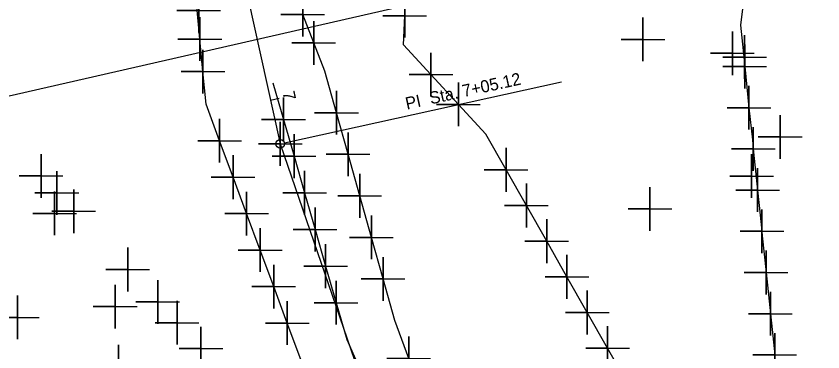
# Model space of a CAD drawing. Extents: x 2260968 to 2264340, y 653057 to 655850.
# Drawn here: x 2261657.4 to 2261749.7, y 655055 to 655093.4 of the extents above; entities that cross this region are included whole.
import ezdxf

# ---------------------------------------------------------------- set-up
doc = ezdxf.new("R2010")
doc.units = 0
for name, color, linetype in [('CL_X_Construction', 7, 'Continuous'), ('Default', 7, 'Continuous'), ('GE_X_CL_10', 7, 'Continuous'), ('GK_Patterns2', 7, 'Continuous')]:
    doc.layers.add(name, color=color, linetype=linetype)

msp = doc.modelspace()

# ---------------------------------------------------------------- linework, layer by layer
at = {"layer": 'CL_X_Construction'}
for p, q in [((2261663.661, 655187.525), (2261687.579, 655078.757)), ((2261663.661, 655187.525), (2261687.579, 655078.757)), ((2261687.579, 655078.757), (2261714.109, 655001.598)), ((2261687.579, 655078.757), (2261714.109, 655001.598))]:
    msp.add_line(p, q, dxfattribs=at)
at = {"layer": 'Default'}
for points in [[(2261678.254, 655093.992), (2261678.254, 655096.492), (2261678.254, 655093.992), (2261675.754, 655093.992), (2261678.254, 655093.992), (2261678.254, 655091.492), (2261678.254, 655093.992), (2261680.754, 655093.992)], [(2261690.155, 655093.53), (2261690.155, 655096.03), (2261690.155, 655093.53), (2261687.655, 655093.53), (2261690.155, 655093.53), (2261690.155, 655091.03), (2261690.155, 655093.53), (2261692.655, 655093.53)], [(2261701.833, 655093.401), (2261701.833, 655095.901), (2261701.833, 655093.401), (2261699.333, 655093.401), (2261701.833, 655093.401), (2261701.833, 655090.901), (2261701.833, 655093.401), (2261704.333, 655093.401)], [(2261740.728, 655096.117), (2261740.257, 655092.312), (2261740.748, 655087.601), (2261741.24, 655082.889), (2261741.625, 655079.201), (2261741.732, 655078.178), (2261741.923, 655076.347), (2261742.223, 655073.466), (2261742.405, 655071.722), (2261742.715, 655068.754), (2261742.769, 655068.23), (2261743.206, 655064.043), (2261743.698, 655059.331), (2261743.887, 655057.515), (2261744.189, 655054.62)], [(2261689.938, 655054.1), (2261688.389, 655058.269), (2261686.839, 655062.438), (2261685.289, 655066.607), (2261683.74, 655070.776), (2261682.19, 655074.945), (2261680.641, 655079.114), (2261679.091, 655083.283), (2261678.737, 655087.012), (2261678.382, 655090.741), (2261678.027, 655094.471)], [(2261678.382, 655090.741), (2261678.382, 655093.241), (2261678.382, 655090.741), (2261675.882, 655090.741), (2261678.382, 655090.741), (2261678.382, 655088.241), (2261678.382, 655090.741), (2261680.882, 655090.741)], [(2261720.425, 654990.805), (2261719.672, 654995.689), (2261718.919, 655000.572), (2261718.166, 655005.456), (2261717.413, 655010.339), (2261716.661, 655015.223), (2261715.064, 655019.556), (2261713.468, 655023.89), (2261711.871, 655028.223), (2261710.275, 655032.556), (2261708.678, 655036.889), (2261707.082, 655041.222), (2261705.485, 655045.556), (2261703.889, 655049.889), (2261702.292, 655054.222), (2261700.696, 655058.555), (2261699.362, 655063.307), (2261698.028, 655068.058), (2261696.694, 655072.81), (2261695.36, 655077.561), (2261694.026, 655082.313), (2261692.692, 655087.064), (2261691.423, 655090.297), (2261690.155, 655093.53)], [(2261727.371, 655051.318), (2261725.05, 655055.396), (2261722.729, 655059.473), (2261720.407, 655063.55), (2261718.086, 655067.627), (2261715.765, 655071.705), (2261713.444, 655075.782), (2261711.123, 655079.859), (2261707.975, 655083.264), (2261704.826, 655086.669), (2261701.677, 655090.074), (2261701.833, 655093.401)], [(2261729.105, 655090.698), (2261729.105, 655093.198), (2261729.105, 655090.698), (2261726.605, 655090.698), (2261729.105, 655090.698), (2261729.105, 655088.198), (2261729.105, 655090.698), (2261731.605, 655090.698)], [(2261691.423, 655090.297), (2261691.423, 655092.797), (2261691.423, 655090.297), (2261688.923, 655090.297), (2261691.423, 655090.297), (2261691.423, 655087.797), (2261691.423, 655090.297), (2261693.923, 655090.297)], [(2261739.351, 655089.119), (2261739.351, 655091.619), (2261739.351, 655089.119), (2261736.851, 655089.119), (2261739.351, 655089.119), (2261739.351, 655086.619), (2261739.351, 655089.119), (2261741.851, 655089.119)], [(2261740.746, 655088.678), (2261740.746, 655091.178), (2261740.746, 655088.678), (2261738.246, 655088.678), (2261740.746, 655088.678), (2261740.746, 655086.178), (2261740.746, 655088.678), (2261743.246, 655088.678)], [(2261678.737, 655087.012), (2261678.737, 655089.512), (2261678.737, 655087.012), (2261676.237, 655087.012), (2261678.737, 655087.012), (2261678.737, 655084.512), (2261678.737, 655087.012), (2261681.237, 655087.012)], [(2261740.748, 655087.601), (2261740.748, 655090.101), (2261740.748, 655087.601), (2261738.248, 655087.601), (2261740.748, 655087.601), (2261740.748, 655085.101), (2261740.748, 655087.601), (2261743.248, 655087.601)], [(2261704.826, 655086.669), (2261704.826, 655089.169), (2261704.826, 655086.669), (2261702.326, 655086.669), (2261704.826, 655086.669), (2261704.826, 655084.169), (2261704.826, 655086.669), (2261707.326, 655086.669)], [(2261686.753, 655085.733), (2261687.959, 655081.541), (2261689.164, 655077.349), (2261690.37, 655073.157), (2261691.575, 655068.965), (2261692.781, 655064.773), (2261693.986, 655060.581), (2261695.192, 655056.389), (2261697.028, 655052.215), (2261698.865, 655048.042), (2261700.701, 655043.868), (2261702.538, 655039.695), (2261704.375, 655035.521), (2261706.211, 655031.348), (2261708.048, 655027.174), (2261709.884, 655023.001), (2261711.721, 655018.827), (2261713.557, 655014.654), (2261714.248, 655009.793), (2261714.939, 655004.932), (2261715.63, 655000.071), (2261716.321, 654995.21), (2261717.012, 654990.35)], [(2261707.975, 655083.264), (2261707.975, 655085.764), (2261707.975, 655083.264), (2261705.475, 655083.264), (2261707.975, 655083.264), (2261707.975, 655080.764), (2261707.975, 655083.264), (2261710.475, 655083.264)], [(2261694.026, 655082.313), (2261694.026, 655084.813), (2261694.026, 655082.313), (2261691.526, 655082.313), (2261694.026, 655082.313), (2261694.026, 655079.813), (2261694.026, 655082.313), (2261696.526, 655082.313)], [(2261741.24, 655082.889), (2261741.24, 655085.389), (2261741.24, 655082.889), (2261738.74, 655082.889), (2261741.24, 655082.889), (2261741.24, 655080.389), (2261741.24, 655082.889), (2261743.74, 655082.889)], [(2261687.959, 655081.541), (2261687.959, 655084.041), (2261687.959, 655081.541), (2261685.459, 655081.541), (2261687.959, 655081.541), (2261687.959, 655079.041), (2261687.959, 655081.541), (2261690.459, 655081.541)], [(2261744.81, 655079.54), (2261744.81, 655082.04), (2261744.81, 655079.54), (2261742.31, 655079.54), (2261744.81, 655079.54), (2261744.81, 655077.04), (2261744.81, 655079.54), (2261747.31, 655079.54)], [(2261680.641, 655079.114), (2261680.641, 655081.614), (2261680.641, 655079.114), (2261678.141, 655079.114), (2261680.641, 655079.114), (2261680.641, 655076.614), (2261680.641, 655079.114), (2261683.141, 655079.114)], [(2261687.579, 655078.757), (2261687.579, 655081.257), (2261687.579, 655078.757), (2261685.079, 655078.757), (2261687.579, 655078.757), (2261687.579, 655076.257), (2261687.579, 655078.757), (2261690.079, 655078.757)], [(2261741.732, 655078.178), (2261741.732, 655080.678), (2261741.732, 655078.178), (2261739.232, 655078.178), (2261741.732, 655078.178), (2261741.732, 655075.678), (2261741.732, 655078.178), (2261744.232, 655078.178)], [(2261689.164, 655077.349), (2261689.164, 655079.849), (2261689.164, 655077.349), (2261686.664, 655077.349), (2261689.164, 655077.349), (2261689.164, 655074.849), (2261689.164, 655077.349), (2261691.664, 655077.349)], [(2261695.36, 655077.561), (2261695.36, 655080.061), (2261695.36, 655077.561), (2261692.86, 655077.561), (2261695.36, 655077.561), (2261695.36, 655075.061), (2261695.36, 655077.561), (2261697.86, 655077.561)], [(2261713.444, 655075.782), (2261713.444, 655078.282), (2261713.444, 655075.782), (2261710.944, 655075.782), (2261713.444, 655075.782), (2261713.444, 655073.282), (2261713.444, 655075.782), (2261715.944, 655075.782)], [(2261660.207, 655075.085), (2261660.207, 655077.585), (2261660.207, 655075.085), (2261657.707, 655075.085), (2261660.207, 655075.085), (2261660.207, 655072.585), (2261660.207, 655075.085), (2261662.707, 655075.085)], [(2261682.19, 655074.945), (2261682.19, 655077.445), (2261682.19, 655074.945), (2261679.69, 655074.945), (2261682.19, 655074.945), (2261682.19, 655072.445), (2261682.19, 655074.945), (2261684.69, 655074.945)], [(2261741.539, 655075.073), (2261741.539, 655077.573), (2261741.539, 655075.073), (2261739.039, 655075.073), (2261741.539, 655075.073), (2261741.539, 655072.573), (2261741.539, 655075.073), (2261744.039, 655075.073)], [(2261662.013, 655073.138), (2261662.013, 655075.638), (2261662.013, 655073.138), (2261659.513, 655073.138), (2261662.013, 655073.138), (2261662.013, 655070.638), (2261662.013, 655073.138), (2261664.513, 655073.138)], [(2261690.37, 655073.157), (2261690.37, 655075.657), (2261690.37, 655073.157), (2261687.87, 655073.157), (2261690.37, 655073.157), (2261690.37, 655070.657), (2261690.37, 655073.157), (2261692.87, 655073.157)], [(2261742.223, 655073.466), (2261742.223, 655075.966), (2261742.223, 655073.466), (2261739.723, 655073.466), (2261742.223, 655073.466), (2261742.223, 655070.966), (2261742.223, 655073.466), (2261744.723, 655073.466)], [(2261696.694, 655072.81), (2261696.694, 655075.31), (2261696.694, 655072.81), (2261694.194, 655072.81), (2261696.694, 655072.81), (2261696.694, 655070.31), (2261696.694, 655072.81), (2261699.194, 655072.81)], [(2261715.765, 655071.705), (2261715.765, 655074.205), (2261715.765, 655071.705), (2261713.265, 655071.705), (2261715.765, 655071.705), (2261715.765, 655069.205), (2261715.765, 655071.705), (2261718.265, 655071.705)], [(2261729.91, 655071.319), (2261729.91, 655073.819), (2261729.91, 655071.319), (2261727.41, 655071.319), (2261729.91, 655071.319), (2261729.91, 655068.819), (2261729.91, 655071.319), (2261732.41, 655071.319)], [(2261661.76, 655070.81), (2261661.76, 655073.31), (2261661.76, 655070.81), (2261659.26, 655070.81), (2261661.76, 655070.81), (2261661.76, 655068.31), (2261661.76, 655070.81), (2261664.26, 655070.81)], [(2261663.953, 655071.047), (2261663.953, 655073.547), (2261663.953, 655071.047), (2261661.453, 655071.047), (2261663.953, 655071.047), (2261663.953, 655068.547), (2261663.953, 655071.047), (2261666.453, 655071.047)], [(2261683.74, 655070.776), (2261683.74, 655073.276), (2261683.74, 655070.776), (2261681.24, 655070.776), (2261683.74, 655070.776), (2261683.74, 655068.276), (2261683.74, 655070.776), (2261686.24, 655070.776)], [(2261691.575, 655068.965), (2261691.575, 655071.465), (2261691.575, 655068.965), (2261689.075, 655068.965), (2261691.575, 655068.965), (2261691.575, 655066.465), (2261691.575, 655068.965), (2261694.075, 655068.965)], [(2261742.715, 655068.754), (2261742.715, 655071.254), (2261742.715, 655068.754), (2261740.215, 655068.754), (2261742.715, 655068.754), (2261742.715, 655066.254), (2261742.715, 655068.754), (2261745.215, 655068.754)], [(2261698.028, 655068.058), (2261698.028, 655070.558), (2261698.028, 655068.058), (2261695.528, 655068.058), (2261698.028, 655068.058), (2261698.028, 655065.558), (2261698.028, 655068.058), (2261700.528, 655068.058)], [(2261718.086, 655067.627), (2261718.086, 655070.127), (2261718.086, 655067.627), (2261715.586, 655067.627), (2261718.086, 655067.627), (2261718.086, 655065.127), (2261718.086, 655067.627), (2261720.586, 655067.627)], [(2261685.289, 655066.607), (2261685.289, 655069.107), (2261685.289, 655066.607), (2261682.789, 655066.607), (2261685.289, 655066.607), (2261685.289, 655064.107), (2261685.289, 655066.607), (2261687.789, 655066.607)], [(2261692.781, 655064.773), (2261692.781, 655067.273), (2261692.781, 655064.773), (2261690.281, 655064.773), (2261692.781, 655064.773), (2261692.781, 655062.273), (2261692.781, 655064.773), (2261695.281, 655064.773)], [(2261670.125, 655064.392), (2261670.125, 655066.892), (2261670.125, 655064.392), (2261667.625, 655064.392), (2261670.125, 655064.392), (2261670.125, 655061.892), (2261670.125, 655064.392), (2261672.625, 655064.392)], [(2261743.206, 655064.043), (2261743.206, 655066.543), (2261743.206, 655064.043), (2261740.706, 655064.043), (2261743.206, 655064.043), (2261743.206, 655061.543), (2261743.206, 655064.043), (2261745.706, 655064.043)], [(2261699.362, 655063.307), (2261699.362, 655065.807), (2261699.362, 655063.307), (2261696.862, 655063.307), (2261699.362, 655063.307), (2261699.362, 655060.807), (2261699.362, 655063.307), (2261701.862, 655063.307)], [(2261720.407, 655063.55), (2261720.407, 655066.05), (2261720.407, 655063.55), (2261717.907, 655063.55), (2261720.407, 655063.55), (2261720.407, 655061.05), (2261720.407, 655063.55), (2261722.907, 655063.55)], [(2261686.839, 655062.438), (2261686.839, 655064.938), (2261686.839, 655062.438), (2261684.339, 655062.438), (2261686.839, 655062.438), (2261686.839, 655059.938), (2261686.839, 655062.438), (2261689.339, 655062.438)], [(2261668.69, 655060.14), (2261668.69, 655062.64), (2261668.69, 655060.14), (2261666.19, 655060.14), (2261668.69, 655060.14), (2261668.69, 655057.64), (2261668.69, 655060.14), (2261671.19, 655060.14)], [(2261673.573, 655060.674), (2261673.573, 655063.174), (2261673.573, 655060.674), (2261671.073, 655060.674), (2261673.573, 655060.674), (2261673.573, 655058.174), (2261673.573, 655060.674), (2261676.073, 655060.674)], [(2261693.986, 655060.581), (2261693.986, 655063.081), (2261693.986, 655060.581), (2261691.486, 655060.581), (2261693.986, 655060.581), (2261693.986, 655058.081), (2261693.986, 655060.581), (2261696.486, 655060.581)], [(2261722.729, 655059.473), (2261722.729, 655061.973), (2261722.729, 655059.473), (2261720.229, 655059.473), (2261722.729, 655059.473), (2261722.729, 655056.973), (2261722.729, 655059.473), (2261725.229, 655059.473)], [(2261743.698, 655059.331), (2261743.698, 655061.831), (2261743.698, 655059.331), (2261741.198, 655059.331), (2261743.698, 655059.331), (2261743.698, 655056.831), (2261743.698, 655059.331), (2261746.198, 655059.331)], [(2261657.5, 655058.91), (2261657.5, 655061.41), (2261657.5, 655058.91), (2261655, 655058.91), (2261657.5, 655058.91), (2261657.5, 655056.41), (2261657.5, 655058.91), (2261660, 655058.91)], [(2261675.778, 655058.297), (2261675.778, 655060.797), (2261675.778, 655058.297), (2261673.278, 655058.297), (2261675.778, 655058.297), (2261675.778, 655055.797), (2261675.778, 655058.297), (2261678.278, 655058.297)], [(2261688.389, 655058.269), (2261688.389, 655060.769), (2261688.389, 655058.269), (2261685.889, 655058.269), (2261688.389, 655058.269), (2261688.389, 655055.769), (2261688.389, 655058.269), (2261690.889, 655058.269)], [(2261678.51, 655055.351), (2261678.51, 655057.851), (2261678.51, 655055.351), (2261676.01, 655055.351), (2261678.51, 655055.351), (2261678.51, 655052.851), (2261678.51, 655055.351), (2261681.01, 655055.351)], [(2261725.05, 655055.396), (2261725.05, 655057.896), (2261725.05, 655055.396), (2261722.55, 655055.396), (2261725.05, 655055.396), (2261725.05, 655052.896), (2261725.05, 655055.396), (2261727.55, 655055.396)], [(2261744.189, 655054.62), (2261744.189, 655057.12), (2261744.189, 655054.62), (2261741.689, 655054.62), (2261744.189, 655054.62), (2261744.189, 655052.12), (2261744.189, 655054.62), (2261746.689, 655054.62)], [(2261702.292, 655054.222), (2261702.292, 655056.722), (2261702.292, 655054.222), (2261699.792, 655054.222), (2261702.292, 655054.222), (2261702.292, 655051.722), (2261702.292, 655054.222), (2261704.792, 655054.222)], [(2261669.08, 655053.26), (2261669.08, 655055.76), (2261669.08, 655053.26), (2261666.58, 655053.26), (2261669.08, 655053.26), (2261669.08, 655050.76), (2261669.08, 655053.26), (2261671.58, 655053.26)]]:
    msp.add_lwpolyline(points, dxfattribs=at)
at = {"layer": 'GE_X_CL_10'}
for p, q in [((2261663.661, 655187.525), (2261687.579, 655078.757)), ((2261688.067, 655078.864), (2261719.769, 655085.836)), ((2261688.067, 655078.864), (2261719.769, 655085.836)), ((2261686.48, 655083.757), (2261687.456, 655083.972)), ((2261686.48, 655083.757), (2261687.456, 655083.972)), ((2261687.579, 655078.757), (2261714.109, 655001.598))]:
    msp.add_line(p, q, dxfattribs=at)
msp.add_circle((2261687.579, 655078.757), 0.5, dxfattribs=at)
msp.add_circle((2261687.579, 655078.757), 0.5, dxfattribs=at)
at = {"layer": 'GK_Patterns2'}
msp.add_line((2261529.27, 655055.229), (2261923.742, 655145.198), dxfattribs=at)

# ---------------------------------------------------------------- texts
at = {"layer": 'GE_X_CL_10'}
for s, rotation, p in [('PI  Sta. 7+05.12', 12.40214, (2261702.079, 655082.662)), ('PI  Sta. 7+05.12', 12.40214, (2261702.079, 655082.662)), ('7', 282.40214, (2261687.823, 655084.634)), ('7', 282.40214, (2261687.823, 655084.634))]:
    msp.add_text(s, height=1.4, rotation=rotation, dxfattribs=at).set_placement(p)

doc.saveas('drawing.dxf')
